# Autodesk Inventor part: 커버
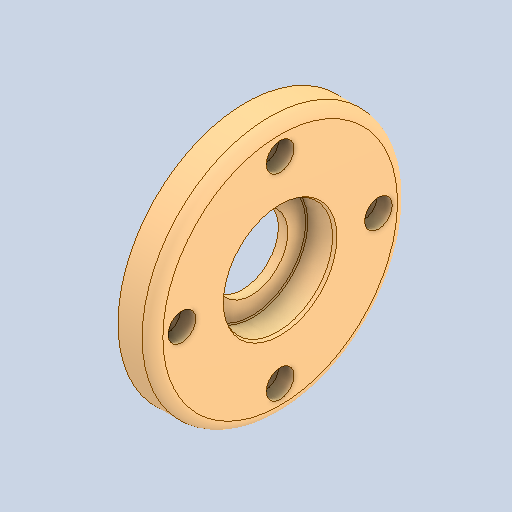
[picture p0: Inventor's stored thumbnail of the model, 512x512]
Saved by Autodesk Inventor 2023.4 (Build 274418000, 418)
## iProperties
Created: 2024-11
Part Number: 커버
Material: 알루미늄 6061
Document SubType Name: Modeling
Designer: EDU
Density: 2.7 g/cm^3
Appearance: 기본값
Author: jhkim
Sending System: Autodesk Inventor 2025
Preprocessor: ST-DEVELOPER v20
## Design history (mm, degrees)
feature "솔리드1"
node "솔리드2"
